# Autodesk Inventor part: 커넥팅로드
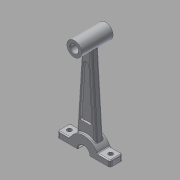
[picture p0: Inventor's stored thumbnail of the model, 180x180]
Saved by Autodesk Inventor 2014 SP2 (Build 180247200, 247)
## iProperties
Created: 2016-11
Part Number: 커넥팅로드
Material: 알루미늄 6061
Document SubType Name: Modeling
Designer: mduedu
Density: 2.71 g/cm^3
Mass: 44.549 g
Surface Area: 86.7069 cm^2
Volume: 16.4387 cm^3
Appearance: 알루미늄 - 평지
Author: mduedu
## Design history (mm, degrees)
sketch "스케치1" dims "d0" = 30, "d3" = 15
  geometry: L1 (0, 0)-(0, 96); L2 (-5, 90.41)-(-10, 11.18); L3 (5, 90.41)-(10, 11.18); C1 r 6 at (0, 0); C2 r 4 at (0, 96); 3 further points
  constraints: 6 end point, 4 coincident, 2 centre point, 2 symmetric about line, 1 vertical, 6 other
  dimensions: "d1" = 12 diameter of C1; "d2" = 8 diameter of C2; "d4" = 96 distance of L1.start L1.end; "d6" = 10 distance from line of L1 L2.end; "d7" = 5 distance from line of L1 L2.start
extrude "돌출1" new body sketch "스케치1" stored distance "d8" = 13; taper "d9" = 0 deg
extrude "돌출2" join sketch "스케치1" stored distance "d10" = 32; taper "d11" = 0 deg
sketch "스케치2"
  geometry: L1 (5, 90.41)-(10, 11.18) reference; L2 (-5, 90.41)-(-10, 11.18) reference; A1 r 7.5 centre (0, 96) between (5, 90.41) and (-5, 90.41) reference; A2 r 15 centre (0, 0) between (10, 11.18) and (-10, 11.18) reference
extrude "돌출3" join sketch "스케치2" stored distance "d12" = 8; taper "d13" = 0 deg
sketch "스케치3"
  geometry: L1 (-2.732, 78.715)-(-6.171, 24.226); L2 (2.732, 78.715)-(6.171, 24.226); L3 (0, 78.5)-(0, 25); A1 r 17.5 centre (0, 96) between (-2.732, 78.715) and (2.732, 78.715); A2 r 25 centre (0, 0) between (6.171, 24.226) and (-6.171, 24.226); 9 further points; 2 other entities
  constraints: 6 end point, 6 point on circle, 2 centre point, 1 symmetric about line, 1 vertical alignment, 6 other
  dimensions: "d18" = 10 dimension on A1; "d19" = 10 dimension on A2; "d20" = 3 dimension on L1
extrude "돌출4" cut sketch "스케치3" distance "d21" = 2; taper "d22" = 0 deg
fillet "모깎기1" dims "d23" = 2
fillet "모깎기2" dims "d24" = 2
fillet "모깎기3" dims "d25" = 1
chamfer "모따기1" distance "d26" = 0.5; stored, may be unused: second distance "d27" = 2, angle "d28" = 45 deg
sketch "스케치4"
  geometry: L1 (-27, -6)-(-13.748, -6); L2 (27, -6)-(27, 6); L3 (27, 6)-(13.748, 6); L4 (-27, 6)-(-27, -6); L5 (-27, -6)-(27, 6); L6 (27, -6)-(-27, 6); L7 (-13.748, 6)-(-27, 6); L8 (13.748, 6)-(-13.748, 6); L9 (13.748, -6)-(27, -6); L10 (-13.748, -6)-(13.748, -6); A1 r 15 centre (0, 0) between (-13.748, 6) and (13.748, 6) reference; 1 further point
  constraints: 20 end point, 10 parallel, 4 point on circle, 3 horizontal, 3 perpendicular, 2 midpoint
  dimensions: "d29" = 54 distance of L1.start L2.start; "d31" = 12 distance of L2.start L2.end
extrude "돌출5" join sketch "스케치4" stored distance "d32" = 0; taper "d33" = 0 deg
fillet "모깎기4" dims "d34" = 2
fillet "모깎기5" dims "d35" = 1
fillet "모깎기6" dims "d36" = 1
sketch "스케치5"
  geometry: L1 (1, 0)-(1, 9) reference; L2 (-18.5, 20.5)-(-33.5, 20.5) reference; L3 (-33.5, -11.5)-(-18.5, -11.5) reference; L4 (-26, 20.5)-(-26, -11.5); 3 further points
  constraints: 2 end point, 2 midpoint, 1 horizontal alignment, 1 symmetric about line
  dimensions: "d37" = 6 distance from line of point (-5, 4.5) L1
feature "분할1"
sketch "스케치7"
  geometry: 2 further points
  constraints: 2 other
hole "구멍2" sketch "스케치7" at (-47, 4.5), (-5, 4.5) diameter "d45" = 4.5; stored, may be unused: countersink angle "d49" = 90 deg, drill point angle "d51" = 0 deg; dims "d46" = 6, "d47" = 4, "d48" = 2, "d50" = 8
node "솔리드1"
mirror "대칭1"
other parameters: "d16" = 4, "d17" = 4
